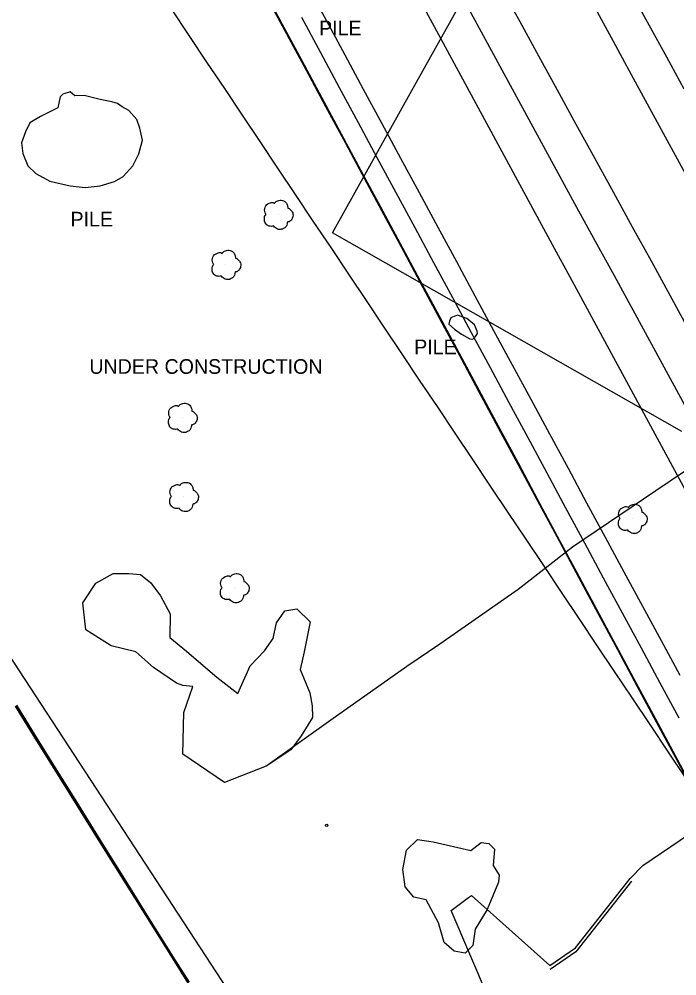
# Model space of a CAD drawing. Extents: x 368532 to 392481, y 10654822 to 10676899.
# Drawn here: x 374349.4 to 374573.7, y 10671447.9 to 10671774.3 of the extents above; entities that cross this region are included whole.
import ezdxf

# ---------------------------------------------------------------- set-up
doc = ezdxf.new("R2010")
doc.units = 0
for name, color, linetype in [('p_Catenary', 7, 'Continuous'), ('p_drainage conc drain', 7, 'Continuous'), ('p_dtm retaining wall', 7, 'Continuous'), ('p_dtm stock pile', 7, 'Continuous'), ('p_road - paved curb', 7, 'Continuous'), ('p_structure constr area', 7, 'Continuous'), ('p_structure fence', 7, 'Continuous'), ('p_structure unidentified', 7, 'Continuous'), ('p_veg tree', 7, 'Continuous'), ('p_veg woods', 7, 'Continuous')]:
    doc.layers.add(name, color=color, linetype=linetype)

msp = doc.modelspace()

# ---------------------------------------------------------------- linework, layer by layer
at = {"layer": 'p_Catenary'}
for points in [[(374447.74, 10671785.74), (374454.08, 10671773.98), (374460.43, 10671762.22), (374466.77, 10671750.46), (374473.12, 10671738.7), (374479.47, 10671726.94), (374485.81, 10671715.18), (374492.16, 10671703.42), (374498.5, 10671691.67), (374504.85, 10671679.91), (374511.19, 10671668.15), (374517.54, 10671656.39), (374523.89, 10671644.63), (374530.23, 10671632.87), (374536.58, 10671621.11), (374542.92, 10671609.35), (374549.27, 10671597.59), (374555.61, 10671585.83), (374561.96, 10671574.07), (374568.31, 10671562.31), (374574.65, 10671550.55)], [(374432.42, 10671785.15), (374439.12, 10671772.67), (374445.82, 10671760.19), (374452.52, 10671747.71), (374459.22, 10671735.23), (374465.92, 10671722.75), (374472.62, 10671710.28), (374479.32, 10671697.8), (374486.02, 10671685.32), (374492.72, 10671672.84), (374499.42, 10671660.36), (374506.12, 10671647.88), (374512.82, 10671635.4), (374519.52, 10671622.92), (374526.22, 10671610.44), (374532.92, 10671597.97), (374539.63, 10671585.49), (374546.33, 10671573.01), (374553.03, 10671560.53), (374559.73, 10671548.05), (374566.43, 10671535.57), (374573.13, 10671523.09), (374579.83, 10671510.61)], [(374484.2, 10671784.22), (374490.91, 10671771.84), (374497.62, 10671759.45), (374504.33, 10671747.06), (374511.04, 10671734.67), (374517.75, 10671722.29), (374524.46, 10671709.9), (374531.16, 10671697.51), (374537.87, 10671685.13), (374544.58, 10671672.74), (374551.29, 10671660.35), (374558, 10671647.96), (374564.71, 10671635.58), (374571.42, 10671623.19), (374578.13, 10671610.8)], [(374513.71, 10671785.22), (374520.1, 10671773.54), (374526.5, 10671761.87), (374532.89, 10671750.2), (374539.29, 10671738.52), (374545.68, 10671726.85), (374552.08, 10671715.17), (374558.48, 10671703.5), (374564.87, 10671691.83), (374571.27, 10671680.15), (374577.66, 10671668.48)], [(374558.18, 10671783.23), (374564.14, 10671772.35), (374570.1, 10671761.46), (374576.06, 10671750.58)], [(374580.05, 10671509.75), (374573.42, 10671522.1), (374566.79, 10671534.46), (374560.15, 10671546.81), (374553.52, 10671559.17), (374546.89, 10671571.52), (374540.25, 10671583.87), (374533.62, 10671596.23), (374526.99, 10671608.58), (374520.36, 10671620.94), (374513.72, 10671633.29), (374507.09, 10671645.64), (374500.46, 10671658), (374493.83, 10671670.35), (374487.19, 10671682.71), (374480.56, 10671695.06), (374473.93, 10671707.41), (374467.29, 10671719.77), (374460.66, 10671732.12), (374454.03, 10671744.48), (374447.4, 10671756.83), (374440.76, 10671769.18), (374434.13, 10671781.54)], [(374501.26, 10671780.44), (374507.64, 10671768.74), (374514.01, 10671757.04), (374520.38, 10671745.35), (374526.76, 10671733.65), (374533.13, 10671721.95), (374539.5, 10671710.25), (374545.87, 10671698.55), (374552.25, 10671686.86), (374558.62, 10671675.16), (374564.99, 10671663.46), (374571.37, 10671651.76), (374577.74, 10671640.06)], [(374401.28, 10671777.81), (374407.32, 10671768.76), (374413.36, 10671759.72), (374419.41, 10671750.68), (374425.45, 10671741.63), (374431.49, 10671732.59), (374437.54, 10671723.55), (374443.58, 10671714.5), (374449.62, 10671705.46), (374455.67, 10671696.42), (374461.71, 10671687.37), (374467.75, 10671678.33), (374473.8, 10671669.29), (374479.84, 10671660.24), (374485.88, 10671651.2), (374491.93, 10671642.16), (374497.97, 10671633.12), (374504.01, 10671624.07), (374510.06, 10671615.03), (374516.1, 10671605.99), (374522.14, 10671596.94), (374528.19, 10671587.9), (374534.23, 10671578.86), (374540.27, 10671569.81), (374546.32, 10671560.77), (374552.36, 10671551.73), (374558.4, 10671542.68), (374564.45, 10671533.64), (374570.49, 10671524.6), (374576.53, 10671515.55)], [(374545.78, 10671778.07), (374551.92, 10671766.79), (374558.06, 10671755.51), (374564.21, 10671744.23), (374570.35, 10671732.95), (374576.49, 10671721.68)], [(374445.72, 10671774.97), (374452.15, 10671763.02), (374458.58, 10671751.07), (374465.01, 10671739.12), (374471.44, 10671727.17), (374477.87, 10671715.21), (374484.3, 10671703.26), (374490.73, 10671691.31), (374497.16, 10671679.36), (374503.59, 10671667.41), (374510.02, 10671655.46), (374516.45, 10671643.51), (374522.88, 10671631.55), (374529.31, 10671619.6), (374535.74, 10671607.65), (374542.17, 10671595.7), (374548.6, 10671583.75), (374555.03, 10671571.8), (374561.46, 10671559.84), (374567.89, 10671547.89), (374574.32, 10671535.94)]]:
    msp.add_lwpolyline(points, dxfattribs=at)
at = {"layer": 'p_drainage conc drain'}
for p, q in [((374562.13, 10671485.56), (374599.3, 10671511.06)), ((374557.76, 10671481.17), (374562.13, 10671485.56)), ((374539.14, 10671457.48), (374557.76, 10671481.17)), ((374498.51, 10671471.62), (374502.6, 10671474.65)), ((374502.6, 10671474.65), (374503.67, 10671475.35)), ((374503.67, 10671475.35), (374530.39, 10671451.45)), ((374496.77, 10671470.21), (374498.51, 10671471.62)), ((374511, 10671437), (374496.77, 10671470.21)), ((374530.39, 10671451.45), (374539.14, 10671457.48))]:
    msp.add_line(p, q, dxfattribs=at)
at = {"layer": 'p_dtm retaining wall'}
for p, q in [((374558.22, 10671480.22), (374539.21, 10671456.11)), ((374539.21, 10671456.11), (374530.5, 10671450.12))]:
    msp.add_line(p, q, dxfattribs=at)
at = {"layer": 'p_dtm stock pile'}
for p, q in [((374363.44, 10671747.79), (374362.69, 10671744.05)), ((374364.31, 10671748.72), (374363.44, 10671747.79)), ((374366.82, 10671749.53), (374364.31, 10671748.72)), ((374368.38, 10671748.2), (374366.82, 10671749.53)), ((374371.64, 10671748.31), (374368.38, 10671748.2)), ((374377.09, 10671746.95), (374371.64, 10671748.31)), ((374381.04, 10671746.12), (374377.09, 10671746.95)), ((374362.69, 10671744.05), (374356.78, 10671741.16)), ((374382.93, 10671745.58), (374381.04, 10671746.12)), ((374384.54, 10671744.37), (374382.93, 10671745.58)), ((374386.82, 10671743.12), (374384.54, 10671744.37)), ((374389.58, 10671740.07), (374386.82, 10671743.12)), ((374356.78, 10671741.16), (374353.11, 10671738.92)), ((374390.65, 10671737.15), (374389.58, 10671740.07)), ((374353.11, 10671738.92), (374351.61, 10671735.94)), ((374391.45, 10671733.01), (374390.65, 10671737.15)), ((374351.61, 10671735.94), (374350.23, 10671732.15)), ((374350.23, 10671732.15), (374350.72, 10671728.48)), ((374390.22, 10671728.38), (374391.45, 10671733.01)), ((374350.72, 10671728.48), (374352.46, 10671724.34)), ((374388.16, 10671724.35), (374390.22, 10671728.38)), ((374352.46, 10671724.34), (374355.18, 10671721.63)), ((374384.93, 10671720.65), (374388.16, 10671724.35)), ((374355.18, 10671721.63), (374359.92, 10671719.01)), ((374381.94, 10671718.94), (374384.93, 10671720.65)), ((374359.92, 10671719.01), (374366.86, 10671717.43)), ((374366.86, 10671717.43), (374371.95, 10671716.94)), ((374371.95, 10671716.94), (374377.07, 10671717.48)), ((374377.07, 10671717.48), (374381.94, 10671718.94)), ((374496.12, 10671671.32), (374495.97, 10671670.22)), ((374496.57, 10671672.38), (374496.12, 10671671.32)), ((374498.89, 10671673.4), (374496.57, 10671672.38)), ((374502.13, 10671672.2), (374498.89, 10671673.4)), ((374504.65, 10671670.09), (374502.13, 10671672.2)), ((374495.97, 10671670.22), (374497.83, 10671668.54)), ((374497.83, 10671668.54), (374500.3, 10671666.89)), ((374505.64, 10671667.92), (374504.65, 10671670.09)), ((374500.3, 10671666.89), (374503.07, 10671665.3)), ((374503.07, 10671665.3), (374504.08, 10671665.12)), ((374504.08, 10671665.12), (374505.03, 10671666.01)), ((374505.03, 10671666.01), (374505.7, 10671667.1)), ((374505.7, 10671667.1), (374505.64, 10671667.92))]:
    msp.add_line(p, q, dxfattribs=at)
at = {"layer": 'p_road - paved curb'}
for p, q in [((374354.38, 10671529.99), (374348.24, 10671539.97)), ((374354.51, 10671530.07), (374348.37, 10671540.05)), ((374354.81, 10671530.25), (374348.67, 10671540.23)), ((374361.38, 10671518.64), (374354.38, 10671529.99)), ((374361.51, 10671518.72), (374354.51, 10671530.07)), ((374361.8, 10671518.9), (374354.81, 10671530.25)), ((374369.21, 10671506.09), (374361.38, 10671518.64)), ((374369.34, 10671506.17), (374361.51, 10671518.72)), ((374369.63, 10671506.35), (374361.8, 10671518.9)), ((374377.65, 10671492.47), (374369.21, 10671506.09)), ((374377.78, 10671492.55), (374369.34, 10671506.17)), ((374378.07, 10671492.73), (374369.63, 10671506.35)), ((374386.05, 10671479.09), (374377.65, 10671492.47)), ((374386.18, 10671479.17), (374377.78, 10671492.55)), ((374386.47, 10671479.36), (374378.07, 10671492.73)), ((374392.73, 10671468.4), (374386.05, 10671479.09)), ((374392.86, 10671468.48), (374386.18, 10671479.17)), ((374393.15, 10671468.66), (374386.47, 10671479.36)), ((374402.27, 10671453.12), (374392.73, 10671468.4)), ((374402.4, 10671453.2), (374392.86, 10671468.48)), ((374402.69, 10671453.39), (374393.15, 10671468.66)), ((374407.1, 10671445.46), (374402.27, 10671453.12)), ((374407.23, 10671445.54), (374402.4, 10671453.2)), ((374407.52, 10671445.73), (374402.69, 10671453.39))]:
    msp.add_line(p, q, dxfattribs=at)
at = {"layer": 'p_structure constr area'}
msp.add_line((374437.23, 10671417.71), (374320.47, 10671596.53), dxfattribs=at)
at = {"layer": 'p_structure fence'}
for p, q in [((374483.34, 10671749.97), (374529.07, 10671832.12)), ((374456.31, 10671701.4), (374483.34, 10671749.97)), ((374575.39, 10671633.62), (374456.31, 10671701.4)), ((374596.79, 10671633.83), (374566.47, 10671613.44)), ((374566.47, 10671613.44), (374538.05, 10671594.14)), ((374538.05, 10671594.14), (374519.55, 10671579.71)), ((374519.55, 10671579.71), (374492.91, 10671561.14)), ((374492.91, 10671561.14), (374481.67, 10671553.42)), ((374481.67, 10671553.42), (374455.72, 10671535.14)), ((374455.72, 10671535.14), (374434.32, 10671519.92))]:
    msp.add_line(p, q, dxfattribs=at)
at = {"layer": 'p_structure unidentified'}
msp.add_circle((374454.32, 10671499.31), 0.375, dxfattribs=at)
at = {"layer": 'p_veg tree'}
for p, q in [((374437.71, 10671707.62), (374437.71, 10671707.62)), ((374419.88, 10671690.56), (374419.88, 10671690.56)), ((374405.02, 10671638.36), (374405.02, 10671638.36)), ((374405.45, 10671611.38), (374405.45, 10671611.38)), ((374558.41, 10671603.89), (374558.41, 10671603.89)), ((374422.73, 10671580.24), (374422.73, 10671580.24))]:
    msp.add_line(p, q, dxfattribs=at)
for points in [[(374436.25, 10671703.72), (374434.7, 10671703.73), (374433.41, 10671704.71), (374433.04, 10671706.17), (374433.15, 10671707.01), (374433.5, 10671707.62), (374433.6, 10671707.73), (374433.54, 10671707.83), (374433.17, 10671708.71), (374433.51, 10671710.61), (374435.1, 10671711.68), (374436.4, 10671711.59), (374436.54, 10671711.54), (374436.61, 10671711.64), (374437.59, 10671712.37), (374439.2, 10671712.49), (374440.56, 10671711.52), (374440.98, 10671710.52), (374441.04, 10671709.97), (374441.02, 10671709.86), (374441.12, 10671709.86), (374441.72, 10671709.56), (374442.56, 10671708.59), (374442.78, 10671707.03), (374442.15, 10671705.79), (374441.19, 10671705.17), (374440.93, 10671705.11), (374440.88, 10671705.06), (374440.87, 10671705), (374440.82, 10671704.55), (374440.48, 10671703.63), (374439.54, 10671702.87), (374438.32, 10671702.55), (374436.82, 10671703.1), (374436.23, 10671703.73)], [(374418.42, 10671686.66), (374416.87, 10671686.67), (374415.58, 10671687.65), (374415.21, 10671689.1), (374415.32, 10671689.95), (374415.67, 10671690.56), (374415.77, 10671690.67), (374415.71, 10671690.76), (374415.34, 10671691.64), (374415.68, 10671693.54), (374417.27, 10671694.61), (374418.57, 10671694.53), (374418.71, 10671694.48), (374418.78, 10671694.58), (374419.76, 10671695.31), (374421.37, 10671695.43), (374422.73, 10671694.46), (374423.15, 10671693.45), (374423.21, 10671692.9), (374423.19, 10671692.79), (374423.29, 10671692.8), (374423.89, 10671692.49), (374424.73, 10671691.52), (374424.95, 10671689.97), (374424.32, 10671688.73), (374423.36, 10671688.11), (374423.1, 10671688.05), (374423.05, 10671688), (374423.04, 10671687.94), (374422.99, 10671687.49), (374422.65, 10671686.57), (374421.71, 10671685.8), (374420.49, 10671685.48), (374418.99, 10671686.04), (374418.4, 10671686.66)], [(374403.56, 10671634.46), (374402, 10671634.47), (374400.72, 10671635.45), (374400.35, 10671636.9), (374400.46, 10671637.75), (374400.81, 10671638.36), (374400.91, 10671638.47), (374400.85, 10671638.56), (374400.47, 10671639.44), (374400.82, 10671641.34), (374402.41, 10671642.41), (374403.71, 10671642.33), (374403.85, 10671642.28), (374403.92, 10671642.38), (374404.89, 10671643.11), (374406.5, 10671643.23), (374407.87, 10671642.26), (374408.28, 10671641.25), (374408.34, 10671640.71), (374408.32, 10671640.59), (374408.43, 10671640.6), (374409.03, 10671640.29), (374409.87, 10671639.32), (374410.09, 10671637.77), (374409.45, 10671636.53), (374408.5, 10671635.91), (374408.24, 10671635.85), (374408.19, 10671635.8), (374408.18, 10671635.74), (374408.12, 10671635.29), (374407.79, 10671634.37), (374406.85, 10671633.6), (374405.63, 10671633.28), (374404.13, 10671633.84), (374403.54, 10671634.47)], [(374403.99, 10671607.48), (374402.43, 10671607.49), (374401.15, 10671608.47), (374400.78, 10671609.93), (374400.89, 10671610.77), (374401.24, 10671611.38), (374401.34, 10671611.49), (374401.28, 10671611.59), (374400.91, 10671612.47), (374401.25, 10671614.37), (374402.84, 10671615.44), (374404.14, 10671615.35), (374404.28, 10671615.3), (374404.35, 10671615.4), (374405.32, 10671616.13), (374406.93, 10671616.25), (374408.3, 10671615.28), (374408.71, 10671614.28), (374408.77, 10671613.73), (374408.76, 10671613.62), (374408.86, 10671613.62), (374409.46, 10671613.32), (374410.3, 10671612.35), (374410.52, 10671610.79), (374409.88, 10671609.55), (374408.93, 10671608.93), (374408.67, 10671608.87), (374408.62, 10671608.82), (374408.61, 10671608.76), (374408.55, 10671608.31), (374408.22, 10671607.39), (374407.28, 10671606.63), (374406.06, 10671606.31), (374404.56, 10671606.86), (374403.97, 10671607.49)], [(374556.95, 10671599.99), (374555.39, 10671600), (374554.11, 10671600.98), (374553.74, 10671602.43), (374553.85, 10671603.28), (374554.2, 10671603.89), (374554.3, 10671604), (374554.24, 10671604.09), (374553.87, 10671604.97), (374554.21, 10671606.87), (374555.8, 10671607.94), (374557.1, 10671607.86), (374557.24, 10671607.81), (374557.31, 10671607.91), (374558.29, 10671608.64), (374559.9, 10671608.76), (374561.26, 10671607.79), (374561.67, 10671606.78), (374561.73, 10671606.23), (374561.72, 10671606.12), (374561.82, 10671606.13), (374562.42, 10671605.82), (374563.26, 10671604.85), (374563.48, 10671603.3), (374562.84, 10671602.06), (374561.89, 10671601.44), (374561.63, 10671601.38), (374561.58, 10671601.33), (374561.57, 10671601.27), (374561.51, 10671600.82), (374561.18, 10671599.9), (374560.24, 10671599.13), (374559.02, 10671598.81), (374557.52, 10671599.37), (374556.93, 10671600)], [(374421.26, 10671576.35), (374419.71, 10671576.36), (374418.42, 10671577.33), (374418.05, 10671578.79), (374418.16, 10671579.64), (374418.51, 10671580.25), (374418.61, 10671580.36), (374418.55, 10671580.45), (374418.18, 10671581.33), (374418.53, 10671583.23), (374420.11, 10671584.3), (374421.41, 10671584.22), (374421.55, 10671584.17), (374421.63, 10671584.26), (374422.6, 10671585), (374424.21, 10671585.12), (374425.57, 10671584.14), (374425.99, 10671583.14), (374426.05, 10671582.59), (374426.03, 10671582.48), (374426.14, 10671582.48), (374426.73, 10671582.18), (374427.57, 10671581.21), (374427.79, 10671579.65), (374427.16, 10671578.42), (374426.2, 10671577.8), (374425.95, 10671577.74), (374425.89, 10671577.69), (374425.89, 10671577.62), (374425.83, 10671577.17), (374425.49, 10671576.26), (374424.55, 10671575.49), (374423.33, 10671575.17), (374421.83, 10671575.73), (374421.24, 10671576.35)]]:
    msp.add_spline(points, degree=3, dxfattribs=at)
at = {"layer": 'p_veg woods'}
for points in [[(374449.45, 10671536.09), (374445.6, 10671529.82), (374442.1, 10671525.06), (374433.65, 10671519.43), (374419.43, 10671513.94), (374405.27, 10671523.56), (374405.55, 10671537.77), (374408.61, 10671546.6), (374405.27, 10671546.95), (374403.07, 10671547.82), (374395.31, 10671553.17), (374389.27, 10671558.52), (374380.87, 10671560.47), (374372.13, 10671566.03), (374371.18, 10671575.19), (374375.62, 10671581.91), (374381.52, 10671585.25), (374386.8, 10671585.16), (374390.85, 10671584.87), (374394.33, 10671582.02), (374397.66, 10671577.62), (374400.89, 10671571.41), (374400.86, 10671563.41), (374406.55, 10671558.69), (374410.54, 10671555.13), (374416.86, 10671549.82), (374424.04, 10671544.29), (374428.21, 10671553.74), (374433.11, 10671558.8), (374436.1, 10671563.08), (374437.15, 10671568.37), (374440.06, 10671572.5), (374444.1, 10671573.16), (374448.61, 10671568.76), (374446.64, 10671558.43), (374445.29, 10671552.49), (374448.52, 10671544.51), (374449.31, 10671540.11)], [(374512.83, 10671479.84), (374509.02, 10671470.58), (374504.89, 10671463.87), (374504.16, 10671458.23), (374501.5, 10671455.63), (374497.72, 10671456.33), (374494.39, 10671459.27), (374492.45, 10671465.98), (374488.24, 10671473.87), (374484, 10671474.82), (374481.07, 10671478.27), (374480.22, 10671484.25), (374481.53, 10671490.83), (374485.28, 10671494.41), (374490.62, 10671493.61), (374503.48, 10671490.75), (374506.96, 10671493.47), (374509.54, 10671493.13), (374511.47, 10671491.15), (374511.08, 10671485.61), (374513.14, 10671482.32)]]:
    msp.add_lwpolyline(points, close=True, dxfattribs=at)

# ---------------------------------------------------------------- texts
at = {"layer": 'p_dtm stock pile'}
for p in [(374449.84, 10671768.79), (374365.1, 10671703.61), (374482.26, 10671660.03)]:
    msp.add_text(' PILE', height=5, dxfattribs=at).set_placement(p)
at = {"layer": 'p_structure constr area'}
msp.add_text('UNDER CONSTRUCTION', height=5, dxfattribs=at).set_placement((374373.38, 10671653.33))

doc.saveas('drawing.dxf')
